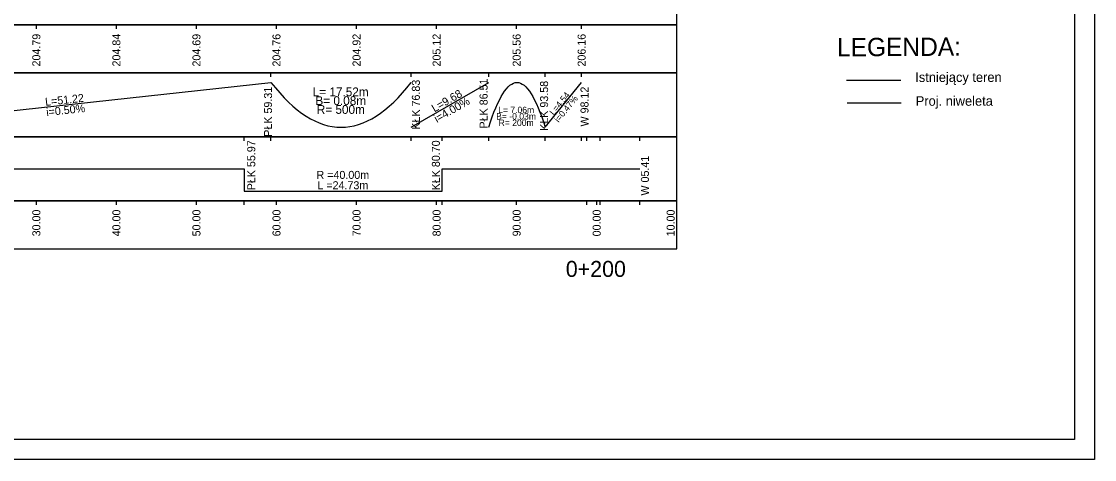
# Model space of a CAD drawing. Extents: x 6512707 to 6513007, y 6022307 to 6022469.
# Drawn here: x 6512872.6 to 6513006.6, y 6022306.7 to 6022361.5 of the extents above; entities that cross this region are included whole.
import ezdxf

# ---------------------------------------------------------------- set-up
doc = ezdxf.new("R2010")
doc.units = 0
for name, color, linetype in [('1', 7, 'Continuous'), ('42', 7, 'Continuous'), ('54', 7, 'Continuous'), ('Level 20', 7, 'Continuous'), ('maxp_ramka_2', 7, 'Continuous'), ('psr-ramka-2', 7, 'Continuous')]:
    doc.layers.add(name, color=color, linetype=linetype)

msp = doc.modelspace()

# ---------------------------------------------------------------- linework, layer by layer
for points in [[(6512852.51, 6022348.26), (6512903.73, 6022353.86)], [(6512903.73, 6022353.86), (6512904.28, 6022353.18), (6512904.82, 6022352.55), (6512905.37, 6022351.96), (6512905.92, 6022351.41), (6512906.47, 6022350.91), (6512907.01, 6022350.45), (6512907.56, 6022350.03), (6512908.11, 6022349.66), (6512908.66, 6022349.33), (6512909.2, 6022349.05), (6512909.75, 6022348.81), (6512910.3, 6022348.61), (6512910.85, 6022348.46), (6512911.39, 6022348.35), (6512911.94, 6022348.28), (6512913.04, 6022348.28), (6512913.58, 6022348.35), (6512914.13, 6022348.46), (6512914.68, 6022348.61), (6512915.23, 6022348.81), (6512915.78, 6022349.05), (6512916.32, 6022349.33), (6512916.87, 6022349.66), (6512917.42, 6022350.03), (6512917.97, 6022350.45), (6512918.51, 6022350.91), (6512919.06, 6022351.41), (6512919.61, 6022351.96), (6512920.16, 6022352.55), (6512920.7, 6022353.18), (6512921.25, 6022353.86)], [(6512921.25, 6022348.26), (6512930.93, 6022353.86)], [(6512930.93, 6022348.26), (6512931.15, 6022348.94), (6512931.37, 6022349.57), (6512931.59, 6022350.16), (6512931.81, 6022350.71), (6512932.03, 6022351.21), (6512932.26, 6022351.67), (6512932.48, 6022352.09), (6512932.7, 6022352.46), (6512932.92, 6022352.79), (6512933.14, 6022353.07), (6512933.36, 6022353.31), (6512933.58, 6022353.51), (6512933.8, 6022353.66), (6512934.02, 6022353.77), (6512934.24, 6022353.84), (6512934.68, 6022353.84), (6512934.9, 6022353.77), (6512935.13, 6022353.66), (6512935.35, 6022353.51), (6512935.57, 6022353.31), (6512935.79, 6022353.07), (6512936.01, 6022352.79), (6512936.23, 6022352.46), (6512936.45, 6022352.09), (6512936.67, 6022351.67), (6512936.89, 6022351.21), (6512937.11, 6022350.71), (6512937.33, 6022350.16), (6512937.55, 6022349.57), (6512937.77, 6022348.94), (6512938, 6022348.26)], [(6512938, 6022348.26), (6512942.54, 6022353.86)], [(6512744.42, 6022343.06), (6512760.65, 6022343.06), (6512760.65, 6022340.26), (6512762.86, 6022340.26), (6512762.86, 6022343.06), (6512778.8, 6022343.06), (6512778.8, 6022345.86), (6512784.03, 6022345.86), (6512784.03, 6022343.06), (6512812.66, 6022343.06), (6512812.66, 6022340.26), (6512834.1, 6022340.26), (6512834.1, 6022343.06), (6512900.39, 6022343.06), (6512900.39, 6022340.26), (6512925.12, 6022340.26), (6512925.12, 6022343.06), (6512943.18, 6022343.06), (6512943.18, 6022343.06), (6512944.85, 6022343.06), (6512944.85, 6022343.06), (6512949.83, 6022343.06)]]:
    msp.add_lwpolyline(points)
at = {"layer": '1'}
msp.add_line((6512975.65, 6022354.17), (6512982.41, 6022354.17), dxfattribs=at)
at = {"layer": '42'}
msp.add_line((6512975.7, 6022351.33), (6512982.46, 6022351.33), dxfattribs=at)
at = {"layer": '54'}
for points in [[(6512744.42, 6022361.06), (6512954.42, 6022361.06), (6512954.42, 6022367.06), (6512744.42, 6022367.06)], [(6512744.42, 6022355.06), (6512954.42, 6022355.06), (6512954.42, 6022361.06), (6512744.42, 6022361.06)], [(6512744.42, 6022347.06), (6512954.42, 6022347.06), (6512954.42, 6022355.06), (6512744.42, 6022355.06)], [(6512744.42, 6022339.06), (6512954.42, 6022339.06), (6512954.42, 6022347.06), (6512744.42, 6022347.06)], [(6512744.42, 6022333.06), (6512954.42, 6022333.06), (6512954.42, 6022339.06), (6512744.42, 6022339.06)]]:
    msp.add_lwpolyline(points, close=True, dxfattribs=at)
for points in [[(6512874.42, 6022360.56), (6512874.42, 6022361.06)], [(6512884.42, 6022360.56), (6512884.42, 6022361.06)], [(6512894.42, 6022360.56), (6512894.42, 6022361.06)], [(6512904.42, 6022360.56), (6512904.42, 6022361.06)], [(6512914.42, 6022360.56), (6512914.42, 6022361.06)], [(6512924.42, 6022360.56), (6512924.42, 6022361.06)], [(6512934.42, 6022360.56), (6512934.42, 6022361.06)], [(6512942.54, 6022360.56), (6512942.54, 6022361.06)], [(6512954.42, 6022360.56), (6512954.42, 6022361.06)], [(6512903.73, 6022354.56), (6512903.73, 6022355.06)], [(6512921.25, 6022354.56), (6512921.25, 6022355.06)], [(6512930.93, 6022354.56), (6512930.93, 6022355.06)], [(6512938, 6022354.56), (6512938, 6022355.06)], [(6512942.54, 6022354.56), (6512942.54, 6022355.06)], [(6512900.39, 6022346.56), (6512900.39, 6022347.06)], [(6512903.73, 6022346.56), (6512903.73, 6022347.06)], [(6512921.25, 6022346.56), (6512921.25, 6022347.06)], [(6512925.12, 6022346.56), (6512925.12, 6022347.06)], [(6512930.93, 6022346.56), (6512930.93, 6022347.06)], [(6512938, 6022346.56), (6512938, 6022347.06)], [(6512942.54, 6022346.56), (6512942.54, 6022347.06)], [(6512943.18, 6022346.56), (6512943.18, 6022347.06)], [(6512944.85, 6022346.56), (6512944.85, 6022347.06)], [(6512949.83, 6022346.56), (6512949.83, 6022347.06)], [(6512874.42, 6022338.56), (6512874.42, 6022339.06)], [(6512884.42, 6022338.56), (6512884.42, 6022339.06)], [(6512894.42, 6022338.56), (6512894.42, 6022339.06)], [(6512900.39, 6022338.56), (6512900.39, 6022339.06)], [(6512904.42, 6022338.56), (6512904.42, 6022339.06)], [(6512914.42, 6022338.56), (6512914.42, 6022339.06)], [(6512924.42, 6022338.56), (6512924.42, 6022339.06)], [(6512925.12, 6022338.56), (6512925.12, 6022339.06)], [(6512934.42, 6022338.56), (6512934.42, 6022339.06)], [(6512943.18, 6022338.56), (6512943.18, 6022339.06)], [(6512944.42, 6022338.56), (6512944.42, 6022339.06)], [(6512944.85, 6022338.56), (6512944.85, 6022339.06)], [(6512949.83, 6022338.56), (6512949.83, 6022339.06)], [(6512954.42, 6022338.56), (6512954.42, 6022339.06)]]:
    msp.add_lwpolyline(points, dxfattribs=at)
at = {"layer": 'maxp_ramka_2'}
for points in [[(6512706.62, 6022455.24), (6513006.62, 6022455.24), (6513006.62, 6022306.74), (6512706.62, 6022306.74)], [(6512719.12, 6022309.24), (6512719.12, 6022452.74), (6513004.12, 6022452.74), (6513004.12, 6022309.24)]]:
    msp.add_lwpolyline(points, close=True, dxfattribs=at)

# ---------------------------------------------------------------- texts
at = {"layer": '1'}
for s, p in [('204.79', (6512874.92, 6022355.86)), ('204.84', (6512884.92, 6022355.86)), ('204.69', (6512894.92, 6022355.85)), ('204.76', (6512904.92, 6022355.85)), ('204.92', (6512914.92, 6022355.86)), ('205.12', (6512924.92, 6022355.86)), ('205.56', (6512934.92, 6022355.85)), ('206.16', (6512943.04, 6022355.85)), ('KŁK 76.83', (6512922.33, 6022347.96)), ('PŁK 86.51', (6512930.79, 6022348.11)), ('KŁK 93.58', (6512938.35, 6022347.82)), ('PŁK 59.31', (6512903.86, 6022347.08)), ('W 98.12', (6512943.4, 6022348.36))]:
    msp.add_text(s, height=1, rotation=90, dxfattribs=at).set_placement(p)
msp.add_text('0+200', height=2, dxfattribs=at).set_placement((6512940.56, 6022329.56))
at = {"layer": '42'}
for s, height, p in [('L= 17.52m', 1.1, (6512908.94, 6022352.14)), ('B= 0.08m', 1.1, (6512909.28, 6022351.04)), ('R= 500m', 1.1, (6512909.45, 6022349.94)), ('L= 7.06m', 0.802, (6512932.11, 6022350.03)), ('B= -0.03m', 0.802, (6512931.86, 6022349.23)), ('R= 200m', 0.802, (6512932.17, 6022348.43))]:
    msp.add_text(s, height=height, dxfattribs=at).set_placement(p)
at = {"layer": '54'}
for s, p in [('PŁK 55.97', (6512901.77, 6022340.39)), ('KŁK 80.70', (6512924.83, 6022340.38)), ('W 05.41', (6512950.95, 6022339.73)), ('30.00', (6512874.92, 6022334.63)), ('40.00', (6512884.92, 6022334.63)), ('50.00', (6512894.92, 6022334.63)), ('60.00', (6512904.92, 6022334.63)), ('70.00', (6512914.92, 6022334.63)), ('80.00', (6512924.92, 6022334.63)), ('90.00', (6512934.92, 6022334.63)), ('00.00', (6512944.92, 6022334.63)), ('10.00', (6512954.16, 6022334.63))]:
    msp.add_text(s, height=1, rotation=90, dxfattribs=at).set_placement(p)
for s, p in [('R =40.00m', (6512909.42, 6022341.81)), ('L =24.73m', (6512909.53, 6022340.52))]:
    msp.add_text(s, height=1, dxfattribs=at).set_placement(p)
at = {"layer": 'Level 20'}
for s, height, rotation, p in [('L=51.22', 1, 6.239, (6512875.57, 6022350.93)), ('L=9.68', 1, 30.0483, (6512924.15, 6022350.11)), ('L=4.54', 0.802, 50.9514, (6512939.06, 6022349.69)), ('i=0.47%', 0.802, 50.9514, (6512939.67, 6022348.8)), ('i=0.50%', 1, 6.239, (6512875.71, 6022349.65)), ('i=4.00%', 1, 30.0483, (6512924.46, 6022348.8))]:
    msp.add_text(s, height=height, rotation=rotation, dxfattribs=at).set_placement(p)
at = {"layer": 'psr-ramka-2'}
for s, height, rotation, p in [('LEGENDA:', 2.292, 0.2979, (6512974.44, 6022357.12)), ('Istniejący teren', 1.2, 0.0505, (6512984.22, 6022353.92)), ('Proj. niweleta', 1.2, 0.0505, (6512984.28, 6022350.95))]:
    msp.add_text(s, height=height, rotation=rotation, dxfattribs=at).set_placement(p)

doc.saveas('drawing.dxf')
